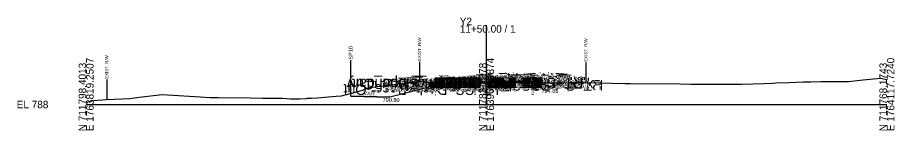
# Model space of a CAD drawing. Extents: x -26 to 1764011, y -10 to 712381.
# Drawn here: x -25.7 to 302.8, y 1490.3 to 1532.5 of the extents above; entities that cross this region are included whole.
import ezdxf

# ---------------------------------------------------------------- set-up
doc = ezdxf.new("R2010")
doc.units = 0
for name, color, linetype in [('Default', 7, 'Continuous'), ('Exist CMT Pavement', 7, 'Continuous'), ('Exist Cross Section Cell', 7, 'Continuous'), ('Exist XS Center Line Elevation Label', 7, 'Continuous'), ('Exist XS Ground Line', 7, 'Continuous'), ('Old_Level_10', 7, 'Continuous'), ('Prop CMT Pvmt Course 1', 7, 'Continuous'), ('Prop CMT Pvmt Course 3', 7, 'Continuous'), ('Prop CMT Pvmt Surface', 7, 'Continuous'), ('Prop CMT Pvmt Surface Shoulder', 7, 'Continuous'), ('Prop CMT Shld Paved Course 1', 7, 'Continuous'), ('Prop CMT Shld Paved Course 3', 7, 'Continuous'), ('Prop CMT Slope Grass', 7, 'Continuous'), ('Prop CMT Subgrade Earthwork', 7, 'Continuous'), ('Prop XS Ditch Standard Text', 7, 'Continuous'), ('Prop XS Earthwork Shape', 7, 'Continuous'), ('Prop XS SE Text', 7, 'Continuous'), ('Prop XS Shear Point Element', 7, 'Continuous'), ('Prop XS Side Slope Text', 7, 'Continuous'), ('Prop XS Wedging', 7, 'Continuous'), ('Scratch_Level_7', 7, 'Continuous')]:
    doc.layers.add(name, color=color, linetype=linetype)

msp = doc.modelspace()

# ---------------------------------------------------------------- linework, layer by layer
at = {"layer": 'Exist CMT Pavement'}
msp.add_lwpolyline([(145.73, 1507.96), (146.3, 1507.99), (146.82, 1508.01), (148.01, 1508.07), (150.26, 1508.16), (150.81, 1508.17), (152.78, 1508.23), (154.38, 1508.22), (155.29, 1508.24), (156.4, 1508.26), (157.8, 1508.3), (159.2, 1508.29), (160.32, 1508.28), (162, 1508.23)], dxfattribs=at)
at = {"layer": 'Exist Cross Section Cell'}
for p, q in [((150, 1500), (150, 1529.67)), ((0, 1500), (150, 1500)), ((150, 1500), (300, 1500))]:
    msp.add_line(p, q, dxfattribs=at)
at = {"layer": 'Exist XS Ground Line'}
msp.add_lwpolyline([(0, 1500.87), (2.87, 1501.54), (7.52, 1501.93), (16.34, 1502.2), (19.9, 1502.71), (28.52, 1503.77), (42.74, 1502.83), (46.38, 1502.67), (49.47, 1502.64), (61.45, 1502.5), (66.05, 1502.37), (73.52, 1502.32), (76.59, 1502.14), (79.89, 1502.12), (82.42, 1502.3), (82.81, 1502.33), (84.49, 1502.42), (86.67, 1502.52), (89.45, 1502.74), (93.68, 1503.06), (95.73, 1503.3), (103.11, 1505.19), (106.26, 1506.36), (109.27, 1506.78), (122.19, 1508.28), (125.12, 1508.61), (136.91, 1507.5), (139.8, 1507.28), (140.55, 1507.4), (145.73, 1507.96), (146.3, 1507.99), (146.82, 1508.01), (148.01, 1508.07), (150.26, 1508.16), (150.81, 1508.17), (152.78, 1508.23), (154.38, 1508.22), (155.29, 1508.24), (156.4, 1508.26), (157.8, 1508.3), (159.2, 1508.29), (160.32, 1508.28), (161.99, 1508.23), (162.83, 1508.2), (164.79, 1508.13), (165.34, 1508.11), (165.86, 1508.11), (167.37, 1507.93), (170.61, 1508.06), (174.15, 1507.95), (181.33, 1508.17), (183, 1508.25), (186.56, 1508.28), (192.08, 1508.16), (201.81, 1507.82), (202.55, 1507.82), (202.97, 1507.83), (203.48, 1507.82), (203.82, 1507.82), (222.56, 1507.72), (226.51, 1507.64), (228.03, 1507.64), (230.06, 1507.63), (242.48, 1507.61), (245.7, 1507.57), (254.18, 1507.84), (257.1, 1508), (258.39, 1508.07), (263.4, 1508.18), (268.6, 1508.42), (271.51, 1508.47), (275.28, 1508.58), (284.36, 1508.64), (285.68, 1508.64), (291.1, 1509.24), (297.58, 1509.89), (300, 1509.4)], dxfattribs=at)
at = {"layer": 'Old_Level_10'}
for p, q in [((124.87, 1515.99), (124.87, 1508.59)), ((187.23, 1515.67), (187.23, 1508.26)), ((7.72, 1509.34), (7.72, 1501.94)), ((145.73, 1507.96), (145.73, 1505.91)), ((167.37, 1507.93), (167.37, 1505.88))]:
    msp.add_line(p, q, dxfattribs=at)
at = {"layer": 'Prop CMT Pvmt Course 1'}
msp.add_line((136.64, 1507.9), (136.97, 1507.91), dxfattribs=at)
for points in [[(150, 1508.43), (136.97, 1507.91)], [(136.97, 1507.66), (150, 1508.18)], [(150, 1508.43), (162, 1508.91)], [(162, 1508.66), (150, 1508.18)], [(150, 1508.18), (150, 1508.43)], [(150, 1508.18), (150, 1508.43)], [(150, 1508.18), (150, 1508.18), (150, 1508.18), (150, 1508.18), (150, 1508.18)], [(162, 1508.91), (162, 1508.66)], [(136.64, 1507.9), (136.64, 1507.65)], [(136.97, 1507.91), (136.97, 1507.66)], [(139.13, 1507.71), (139.13, 1507.71)]]:
    msp.add_lwpolyline(points, dxfattribs=at)
msp.add_lwpolyline([(150, 1508.18), (150, 1508.18), (150, 1508.18), (150, 1508.18)], close=True, dxfattribs=at)
at = {"layer": 'Prop CMT Pvmt Course 3'}
for p, q in [((136.97, 1507.66), (136.64, 1507.65)), ((136.64, 1507.23), (136.97, 1507.24))]:
    msp.add_line(p, q, dxfattribs=at)
for points in [[(145.73, 1508.01), (136.97, 1507.66)], [(162, 1508.66), (162, 1508.24)], [(136.64, 1507.65), (136.64, 1507.23)], [(136.97, 1507.24), (145.73, 1507.59)]]:
    msp.add_lwpolyline(points, dxfattribs=at)
at = {"layer": 'Prop CMT Pvmt Surface'}
msp.add_line((136.64, 1507.9), (136.97, 1507.91), dxfattribs=at)
for points in [[(150, 1508.43), (136.97, 1507.91)], [(150, 1508.43), (162, 1508.91)]]:
    msp.add_lwpolyline(points, dxfattribs=at)
at = {"layer": 'Prop CMT Pvmt Surface Shoulder'}
for points in [[(162, 1508.91), (162, 1508.91)], [(136.64, 1507.9), (136.64, 1507.9)], [(136.97, 1507.91), (136.97, 1507.91)]]:
    msp.add_lwpolyline(points, dxfattribs=at)
at = {"layer": 'Prop CMT Shld Paved Course 1'}
for points in [[(162, 1508.91), (162, 1508.91)], [(162, 1508.91), (162.26, 1508.66)], [(162, 1508.66), (162, 1508.91)], [(162.26, 1508.66), (162, 1508.66)], [(136.64, 1507.9), (136.38, 1507.64)], [(136.38, 1507.64), (136.64, 1507.65)], [(136.64, 1507.9), (136.64, 1507.9)], [(136.64, 1507.65), (136.64, 1507.9)], [(136.97, 1507.91), (136.97, 1507.91)], [(136.97, 1507.66), (136.97, 1507.91)]]:
    msp.add_lwpolyline(points, dxfattribs=at)
at = {"layer": 'Prop CMT Shld Paved Course 3'}
for points in [[(162, 1508.66), (162.26, 1508.66)], [(162, 1508.33), (162, 1508.66)], [(162.68, 1508.23), (162, 1508.24)], [(162.26, 1508.66), (162.68, 1508.23)], [(136.38, 1507.64), (135.96, 1507.22)], [(135.96, 1507.22), (136.64, 1507.23)], [(136.64, 1507.65), (136.38, 1507.64)], [(136.64, 1507.31), (136.64, 1507.65)], [(136.97, 1507.24), (136.97, 1507.66)]]:
    msp.add_lwpolyline(points, dxfattribs=at)
at = {"layer": 'Prop CMT Slope Grass'}
for q in [(99.12, 1504.17), (113.76, 1502.8)]:
    msp.add_line((99.12, 1503.17), q, dxfattribs=at)
for points in [[(162, 1508.91), (166, 1508.83), (174, 1506.83), (179.09, 1508.1)], [(136.64, 1507.9), (132.97, 1507.6), (113.76, 1502.8)]]:
    msp.add_lwpolyline(points, dxfattribs=at)
at = {"layer": 'Prop CMT Subgrade Earthwork'}
for p, q in [((145.73, 1507.59), (145.73, 1507.96)), ((162, 1508.23), (162, 1508.24)), ((162.68, 1508.23), (162, 1508.24)), ((135.96, 1507.22), (136.64, 1507.23)), ((136.97, 1507.24), (136.64, 1507.23)), ((145.73, 1507.59), (136.97, 1507.24))]:
    msp.add_line(p, q, dxfattribs=at)
for points in [[(163.34, 1508.88), (162.68, 1508.23)], [(135.38, 1507.8), (135.96, 1507.22)]]:
    msp.add_lwpolyline(points, dxfattribs=at)
at = {"layer": 'Prop XS Earthwork Shape'}
for points in [[(99.12, 1504.17), (103.11, 1505.19), (106.26, 1506.36), (109.27, 1506.78), (122.19, 1508.28), (125.12, 1508.61), (134.53, 1507.73), (132.97, 1507.6), (113.76, 1502.8), (99.12, 1503.17)], [(145.73, 1507.59), (140.42, 1507.38), (140.55, 1507.4), (145.73, 1507.96)], [(165.34, 1508.11), (165.86, 1508.11), (167.37, 1507.93), (169.3, 1508.01), (166, 1508.83), (163.34, 1508.88), (162.68, 1508.23), (162, 1508.24), (162, 1508.23), (162.83, 1508.2), (164.79, 1508.13)], [(174, 1506.83), (179.09, 1508.1), (174.15, 1507.95), (170.61, 1508.06), (169.3, 1508.01)], [(135.38, 1507.8), (135.54, 1507.63), (134.53, 1507.73)], [(139.17, 1507.33), (136.97, 1507.24), (136.64, 1507.23), (135.96, 1507.22), (135.54, 1507.63), (136.91, 1507.5)], [(139.17, 1507.33), (139.8, 1507.28), (140.42, 1507.38)]]:
    msp.add_lwpolyline(points, close=True, dxfattribs=at)
at = {"layer": 'Prop XS Shear Point Element'}
msp.add_line((99.12, 1503.94), (99.12, 1516.54), dxfattribs=at)
at = {"layer": 'Prop XS Wedging'}
for p, q in [((150, 1508.18), (145.73, 1508.01)), ((145.73, 1507.96), (145.73, 1508.09)), ((145.73, 1508.01), (145.73, 1507.96)), ((145.73, 1507.96), (146.3, 1507.99)), ((159.19, 1508.55), (150, 1508.18)), ((158.95, 1508.29), (150.01, 1507.93)), ((157.8, 1508.3), (158.95, 1508.29)), ((159.19, 1508.55), (158.95, 1508.29)), ((159.19, 1508.55), (158.95, 1508.29)), ((158.95, 1508.29), (159.19, 1508.55)), ((158.95, 1508.29), (159.2, 1508.29)), ((162, 1508.66), (159.19, 1508.55)), ((159.2, 1508.29), (160.32, 1508.28)), ((162, 1508.23), (162, 1508.24))]:
    msp.add_line(p, q, dxfattribs=at)
for points in [[(146.3, 1507.99), (146.82, 1508.01), (148.01, 1508.07), (150.26, 1508.16), (150.81, 1508.17), (152.78, 1508.23)], [(152.78, 1508.23), (154.38, 1508.22), (155.29, 1508.24), (156.4, 1508.26), (157.8, 1508.3)], [(160.32, 1508.28), (161.99, 1508.23), (162, 1508.23)], [(162, 1508.24), (162, 1508.33), (162, 1508.66)]]:
    msp.add_lwpolyline(points, dxfattribs=at)

# ---------------------------------------------------------------- texts
at = {"layer": 'Default'}
msp.add_text('-', height=0.0001, dxfattribs=at).set_placement((0, 1500))
at = {"layer": 'Exist Cross Section Cell'}
for s, p in [('Y2', (140, 1529.67)), ('11+50.00 / 1', (140, 1526.87)), ('EL 788', (-26, 1498.6))]:
    msp.add_text(s, height=2.8, dxfattribs=at).set_placement(p)
for s, p in [('N 711798.4013', (0, 1490)), ('E 1763819.2507', (2.8, 1490)), ('N 711783.2878', (150, 1490)), ('E 1763968.4874', (152.8, 1490)), ('N 711768.1743', (300, 1490)), ('E 1764117.7240', (302.8, 1490))]:
    msp.add_text(s, height=2.8, rotation=90, dxfattribs=at).set_placement(p)
at = {"layer": 'Exist XS Center Line Elevation Label'}
msp.add_text('796.15', height=1, dxfattribs=at).set_placement((147.99, 1506.15))
at = {"layer": 'Old_Level_10'}
for s, height, p in [('EXIST. R/W', 1.181, (125.46, 1516.29)), ('EXIST. R/W', 1.181, (187.82, 1515.97)), ('EXIST. R/W', 1.181, (8.31, 1509.64)), ('EOP', 0.787, (146.12, 1503.52)), ('EOP', 0.787, (167.76, 1503.48))]:
    msp.add_text(s, height=height, rotation=90, dxfattribs=at).set_placement(p)
at = {"layer": 'Prop XS Ditch Standard Text'}
for s, p in [('794.83', (170.6, 1504.34)), ('790.80', (111.09, 1500.97))]:
    msp.add_text(s, height=1.5, dxfattribs=at).set_placement(p)
at = {"layer": 'Prop XS SE Text'}
for p in [(153.34, 1509.57), (140.82, 1509.06)]:
    msp.add_text('0.040', height=1.5, rotation=2.2906, dxfattribs=at).set_placement(p)
at = {"layer": 'Prop XS Shear Point Element'}
msp.add_text('SP10', height=1.5, rotation=90, dxfattribs=at).set_placement((99.9, 1516.78))
at = {"layer": 'Prop XS Side Slope Text'}
for s, rotation, p in [('4:1', 14.0362, (127.63, 1507.03)), ('4:1', 345.9638, (166.22, 1509.31)), ('4:1', 345.9638, (166.26, 1509.3)), ('4:1', 14.0362, (176.79, 1508.06)), ('VAR.', 357.5667, (103.87, 1503.44))]:
    msp.add_text(s, height=1.5, rotation=rotation, dxfattribs=at).set_placement(p)
at = {"layer": 'Scratch_Level_7'}
for s, p in [('RT_PV1_OEEOP', (170.2, 1510.18)), ('LT_PV1_OEEOP', (169.7, 1510.18)), ('RT_PV2_OEEOP', (171.21, 1510.18)), ('LT_PV2_OEEOP', (170.71, 1510.18)), ('RT_PV1_IEEOP', (169.32, 1510.18)), ('LT_PV1_IEEOP', (168.82, 1510.18)), ('RT_PV2_IEEOP', (170.33, 1510.18)), ('LT_PV2_IEEOP', (169.82, 1510.18)), ('PV1_PGL', (160.68, 1510.43)), ('PV2_PGL', (161.68, 1510.18)), ('RT_PS3_Shelf_Out', (187.28, 1510.32)), ('RT_PV1_OEOT', (180.14, 1510.91)), ('RT_PS1_OEOP', (180.41, 1510.91)), ('RT_PV2_OEOT', (181.15, 1510.66)), ('RT_PV3_OEOT', (181.18, 1510.33)), ('RT_PS2_OEOP', (181.67, 1510.66)), ('RT_PS3_OEOP', (182.04, 1510.32)), ('RT_GS_OS_CTL', (186.12, 1510.59)), ('LT_SS_Ditch_Base_Out', (154.69, 1507.59)), ('Exterior Boundary', (140.5, 1509.65)), ('LT_Slope_Cut', (133.8, 1509.65)), ('LT_Sub_OSS_DLT', (152.98, 1508.85)), ('LT_Sub_Trench_Out', (161.47, 1508.97)), ('LT_GS_OS_CTL', (152.58, 1509.59)), ('LT_PS3_Shelf_Out', (160.56, 1509.31)), ('LT_PV1_OEOT', (154.6, 1509.91)), ('LT_PS1_OEOP', (154.87, 1509.91)), ('LT_PS3_OEOP', (155.31, 1509.31)), ('LT_PS2_OEOP', (155.62, 1509.65)), ('LT_PV2_OEOT', (155.61, 1509.66)), ('LT_PV3_OEOT', (155.64, 1509.33)), ('LT_Sub_OEOT', (155.07, 1508.99)), ('RT_PV3_OEEOP', (171.24, 1509.85)), ('RT_Sub_OEEOP', (170.67, 1509.51)), ('LT_PV3_OEEOP', (170.74, 1509.85)), ('LT_Sub_OEEOP', (170.17, 1509.51)), ('RT_Sub_Trench_Out', (188.88, 1509.98)), ('RT_Sub_OEOT', (180.61, 1509.99)), ('RT_Sub_OSS_DLT', (193.35, 1509.16)), ('Exterior Boundary', (193.67, 1509.16)), ('RT_Slope_Fill', (186.25, 1509.97))]:
    msp.add_text(s, height=4, rotation=180, dxfattribs=at).set_placement(p)

doc.saveas('drawing.dxf')
